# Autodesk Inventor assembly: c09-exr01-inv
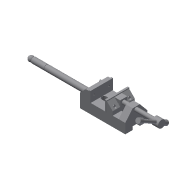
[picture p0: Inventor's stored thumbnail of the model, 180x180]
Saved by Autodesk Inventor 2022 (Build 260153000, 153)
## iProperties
Created: 2011-07
Part Number: c09-exr01-inv
Document SubType Name: Assembly
Designer: CadCim
Author: CadCim
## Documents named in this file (9)
- D:\PROJECTS_2021\Resources\Tutorial Files\c13_Inv_2022_tut\c13_Inv_tut_2022\c13-tut02-inv\Drill Press vice\Drill Press Vice\c09-exr01-inv.iam
- D:\PROJECTS_2021\Resources\Tutorial Files\c13_Inv_2022_tut\c13_Inv_tut_2022\c13-tut02-inv\Drill Press vice\Drill Press Vice\Base.ipt
- D:\PROJECTS_2021\Resources\Tutorial Files\c13_Inv_2022_tut\c13_Inv_tut_2022\c13-tut02-inv\Drill Press vice\Drill Press Vice\Jaw Face.ipt
- D:\PROJECTS_2021\Resources\Tutorial Files\c13_Inv_2022_tut\c13_Inv_tut_2022\c13-tut02-inv\Drill Press vice\Drill Press Vice\Movable Jaw.ipt
- D:\PROJECTS_2021\Resources\Tutorial Files\c13_Inv_2022_tut\c13_Inv_tut_2022\c13-tut02-inv\Drill Press vice\Drill Press Vice\Safety Handle.ipt
- D:\PROJECTS_2021\Resources\Tutorial Files\c13_Inv_2022_tut\c13_Inv_tut_2022\c13-tut02-inv\Drill Press vice\Drill Press Vice\Clamp Screw.ipt
- D:\PROJECTS_2021\Resources\Tutorial Files\c13_Inv_2022_tut\c13_Inv_tut_2022\c13-tut02-inv\Drill Press vice\Drill Press Vice\Clamp Screw Handle.ipt
- D:\PROJECTS_2021\Resources\Tutorial Files\c13_Inv_2022_tut\c13_Inv_tut_2022\c13-tut02-inv\Drill Press vice\Drill Press Vice\Handle Stop.ipt
- D:\PROJECTS_2021\Resources\Tutorial Files\c13_Inv_2022_tut\c13_Inv_tut_2022\c13-tut02-inv\Drill Press vice\Drill Press Vice\Cap Screw.ipt
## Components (13 placed, 8 different names)
1. Base:1 — Insert:3, Insert:9, Insert:10, Mate:8, Mate:9, Mate:12, Mate:13
2. Jaw Face:1 — Mate:10, Mate:11, Mate:12
3. Movable Jaw:1 — Mate:3, Insert:4, Insert:11, Insert:12, Mate:9, Mate:13, Mate:15
4. Safety Handle:1 — Insert:3
5. Clamp Screw:1 — Mate:3, Insert:4, Mate:4, Mate:6, Mate:8
6. Clamp Screw Handle:1 — Mate:4, Insert:7, Insert:8
7. Jaw Face:2 — Mate:14, Mate:15
8. Handle Stop:1 — Insert:7, Mate:6
9. Handle Stop:2 — Insert:8
10. Cap Screw:1 — Insert:12
11. Cap Screw:2 — Insert:11, Mate:14
12. Cap Screw:3 — Insert:10, Mate:11
13. Cap Screw:4 — Insert:9, Mate:10
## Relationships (19: Mate 11, Insert 8)
- Insert:3: Base:1 ↔ Safety Handle:1
- Mate:3: Movable Jaw:1 ↔ Clamp Screw:1
- Insert:4: Movable Jaw:1 ↔ Clamp Screw:1
- Mate:4: Clamp Screw:1 ↔ Clamp Screw Handle:1
- Insert:7: Clamp Screw Handle:1 ↔ Handle Stop:1
- Insert:8: Clamp Screw Handle:1 ↔ Handle Stop:2
- Mate:6: Clamp Screw:1 ↔ Handle Stop:1
- Insert:9: Base:1 ↔ Cap Screw:4
- Insert:10: Base:1 ↔ Cap Screw:3
- Insert:11: Movable Jaw:1 ↔ Cap Screw:2
- Insert:12: Movable Jaw:1 ↔ Cap Screw:1
- Mate:8: Base:1 ↔ Clamp Screw:1
- Mate:9: Base:1 ↔ Movable Jaw:1
- Mate:10: Jaw Face:1 ↔ Cap Screw:4
- Mate:11: Jaw Face:1 ↔ Cap Screw:3
- Mate:12: Base:1 ↔ Jaw Face:1
- Mate:13: Base:1 ↔ Movable Jaw:1
- Mate:14: Jaw Face:2 ↔ Cap Screw:2
- Mate:15: Movable Jaw:1 ↔ Jaw Face:2
